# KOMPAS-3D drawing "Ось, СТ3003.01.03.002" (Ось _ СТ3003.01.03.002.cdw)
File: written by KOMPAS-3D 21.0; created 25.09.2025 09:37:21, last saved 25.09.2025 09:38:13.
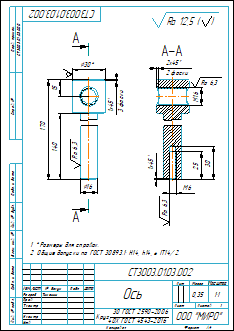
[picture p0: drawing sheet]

Sheet 1: A4, portrait

Document properties: Полное имя файла: C:\Users\1\Yandex.Disk\Документы\Новая папка\Стапель №2\Стапель _ СТ3003.00.00.000\Опора _ СТ3003.01.00.000\2D\Струбцина _ СТ3003.01.03.000\Ось _ СТ3003.01.03.002.cdw; Знак неуказанной шероховатости: 4; Параметр неуказанной шероховатости: Ra 12,5; Масса: 0.346686

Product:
- Part/product: Ось  | designation СТ3003.01.03.002
    Материал: Круг$d30 ГОСТ 2590-2006;40Х ГОСТ 4543-2016$ (density 7850 kg/m3)
    Масса: 0.346686

Title block, sheet 1: Наименование: Ось; designation: СТ3003.01.03.002; Материал: Круг 30 ГОСТ 2590-2006 40Х ГОСТ 4543-2016; Масса: 0,35; Количество листов документа: 1; organisation: ООО "МИРО"; Форматы листов документа: A4; Разработал: Тимонин

Views: Вид 1, Справа, Разрез А-А
Referenced files in C:\Users\1\Yandex.Disk\Документы\Новая папка\Стапель №2\Стапель _ СТ3003.00.00.000\Опора _ СТ3003.01.00.000\3D\Струбцина _ СТ3003.01.03.000\: Ось _ СТ3003.01.03.002.m3d
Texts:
  Ra 6,3
  Ra 12,5
  Ra 12,5 ( )
  СТ3003.01.03.000
  СТ3003.01.03.002 Ось
Dimensions and other numbers on the sheet: 30; 15; 16; 140; 170; 1; 3 фаски; 2; 2 фаски; 6; 25; 1:1; 0,35

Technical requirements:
  *Размеры для справок.
  Общие допуски по ГОСТ 30893.1: Н14, h14, ± IT14/2.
